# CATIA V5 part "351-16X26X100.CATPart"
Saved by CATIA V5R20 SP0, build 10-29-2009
Part number: 351-16X26X100
Definition: NONE
Nomenclature: 351-16X26X100
Source: Unknown
Description: 351-16X26X100
Bounding box of the stored display mesh (mm): x -5 to 95, y -13 to 13, z -13 to 13
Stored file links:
  C:\Users\Utente\Desktop\IO LAVORO\3D X SITO CF\X SITO\PLASTICA\351\351-16X26X100.CATPart
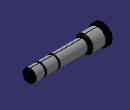
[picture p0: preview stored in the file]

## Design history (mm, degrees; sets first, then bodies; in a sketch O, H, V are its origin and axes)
Body1 "351-16X26X100" (main body)
  Solid1: solid without history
